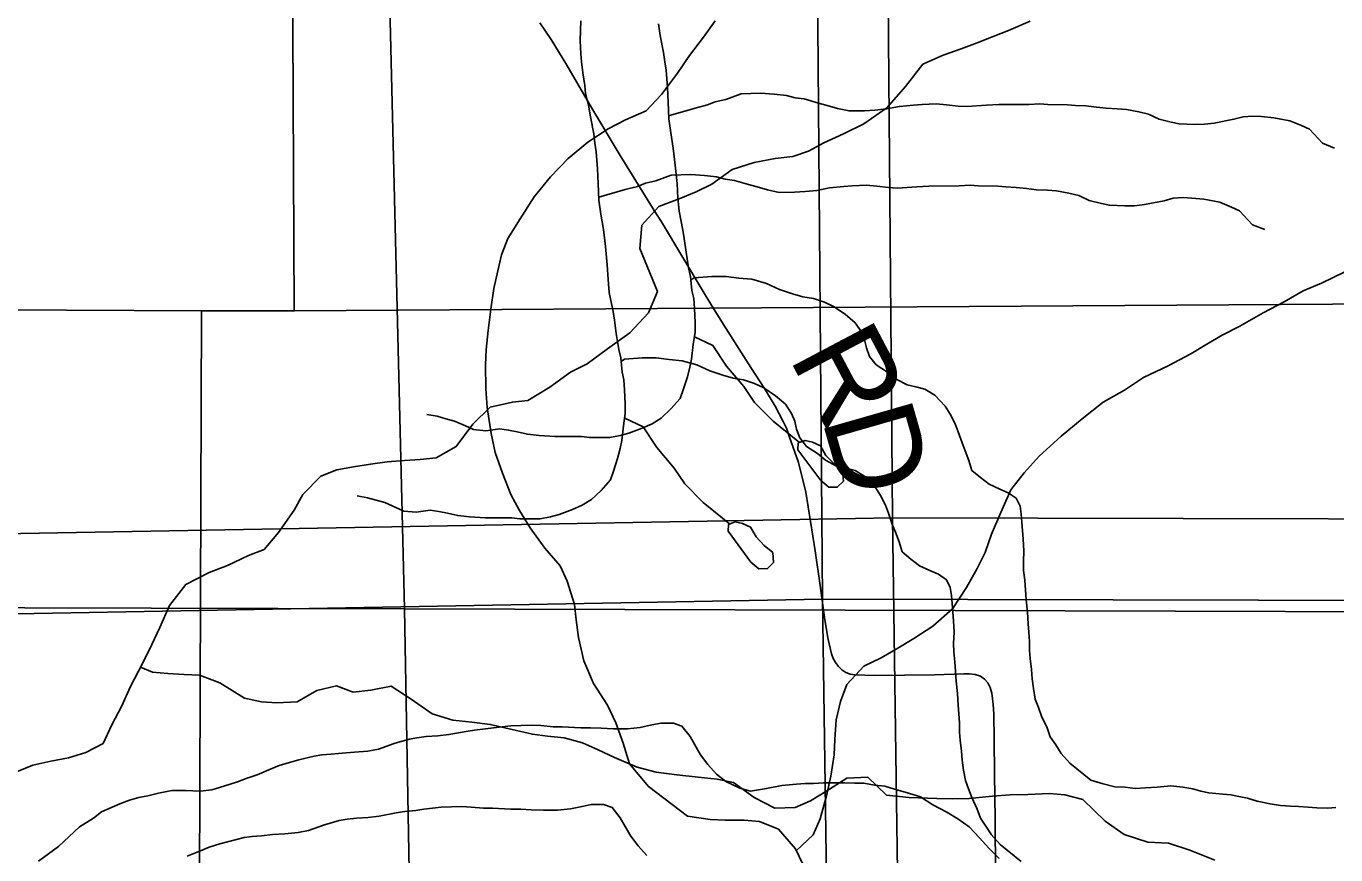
# Model space of a CAD drawing. Extents: x -21.1 to 50.3, y -4.9 to 22.1.
# Drawn here: x 6.307 to 7.119, y 16.789 to 17.303 of the extents above; entities that cross this region are included whole.
import ezdxf

# ---------------------------------------------------------------- set-up
doc = ezdxf.new("R2010")
doc.units = 0
for name, color, linetype in [('GM_X_Minor_Lake', 7, 'Continuous'), ('GM_X_Minor_River', 7, 'Continuous'), ('GM_X_Section', 7, 'Continuous'), ('GM_X_Township_Road', 7, 'Continuous'), ('GM_X_Township_Road_Text', 7, 'Continuous')]:
    doc.layers.add(name, color=color, linetype=linetype)

msp = doc.modelspace()

# ---------------------------------------------------------------- linework, layer by layer
at = {"layer": 'GM_X_Minor_Lake'}
for points in [[(6.79961, 17.0207), (6.80459, 17.01658), (6.8099, 17.01663), (6.81365, 17.02047), (6.8132, 17.02653), (6.80784, 17.03103), (6.80285, 17.03629), (6.79937, 17.04232), (6.79442, 17.04455), (6.78985, 17.04564), (6.7857, 17.04408), (6.78537, 17.0399)], [(6.78537, 17.0399), (6.79961, 17.0207)], [(6.75633, 16.97018), (6.7613, 16.96606), (6.76661, 16.96611), (6.77036, 16.96995), (6.76991, 16.97602), (6.76455, 16.98051), (6.75956, 16.98577), (6.75608, 16.99181), (6.75113, 16.99403), (6.74656, 16.99512), (6.74241, 16.99356), (6.74208, 16.98938)], [(6.74208, 16.98938), (6.75633, 16.97018)]]:
    msp.add_lwpolyline(points, dxfattribs=at)
at = {"layer": 'GM_X_Minor_River'}
for points in [[(6.29709, 16.83866), (6.31085, 16.84415), (6.32191, 16.84665), (6.33295, 16.84876), (6.34364, 16.85201), (6.35436, 16.85755), (6.35986, 16.86924), (6.36612, 16.88092), (6.37124, 16.89262), (6.37907, 16.9077), (6.38456, 16.91901), (6.38966, 16.92957), (6.39557, 16.94315), (6.40565, 16.9563), (6.4202, 16.96367), (6.43166, 16.96806), (6.44467, 16.97432), (6.45423, 16.97797), (6.46313, 16.98847), (6.47284, 17.00238), (6.47831, 17.01218), (6.48949, 17.0234), (6.49943, 17.02743), (6.50972, 17.02917), (6.52038, 17.03091), (6.53066, 17.03227), (6.54131, 17.03325), (6.55119, 17.03386), (6.56108, 17.03485), (6.57334, 17.04188), (6.58381, 17.05578), (6.59461, 17.06625), (6.60834, 17.06946), (6.61785, 17.07046), (6.63165, 17.0786), (6.64433, 17.08791), (6.65466, 17.09307), (6.66734, 17.10237), (6.68117, 17.11242), (6.69276, 17.12478), (6.69828, 17.13799), (6.6873, 17.16475), (6.68866, 17.17917), (6.6991, 17.19078), (6.71285, 17.19589), (6.72241, 17.19992), (6.73198, 17.20472), (6.74465, 17.21364), (6.75839, 17.21799), (6.77135, 17.22045), (6.78238, 17.22181), (6.79193, 17.22508), (6.8015, 17.23025), (6.81374, 17.23576), (6.82638, 17.24203), (6.84059, 17.25207), (6.85218, 17.26519), (6.86303, 17.27908), (6.87566, 17.28459), (6.88673, 17.2886), (6.89666, 17.29225), (6.9066, 17.29628), (6.91615, 17.29993), (6.92954, 17.3058)], [(6.65075, 17.30598), (6.65044, 17.29382), (6.65087, 17.28547), (6.65128, 17.28053), (6.65208, 17.2737), (6.65326, 17.26573), (6.65367, 17.26079), (6.65562, 17.25358), (6.6568, 17.24637), (6.65876, 17.23575), (6.65955, 17.23005), (6.66035, 17.22474), (6.66117, 17.21411), (6.6616, 17.20499), (6.66203, 17.19474), (6.66323, 17.18601), (6.6648, 17.17652), (6.666, 17.16589), (6.66721, 17.1545), (6.66764, 17.14539), (6.66845, 17.13741), (6.6708, 17.12565), (6.67159, 17.12033), (6.67277, 17.11198), (6.67435, 17.10211), (6.67552, 17.0968), (6.67634, 17.08807), (6.6775, 17.08314), (6.67792, 17.07706), (6.67835, 17.06833), (6.67838, 17.06225), (6.67728, 17.05465), (6.67619, 17.04552), (6.67508, 17.04058), (6.67359, 17.03449), (6.67097, 17.0265), (6.6691, 17.02117), (6.66342, 17.01468), (6.65737, 17.00895), (6.65168, 17.0055), (6.6456, 17.00281), (6.63724, 16.99972), (6.63192, 16.99818), (6.62546, 16.997), (6.6129, 16.99693), (6.60795, 16.99767), (6.59158, 16.99758), (6.58168, 16.99828), (6.57444, 16.999), (6.56796, 17.00049), (6.56263, 17.0016), (6.55729, 17.00233), (6.54855, 17.00114), (6.54093, 17.00186), (6.53597, 17.00411), (6.5291, 17.00711), (6.52376, 17.0086), (6.51843, 17.01009), (6.51195, 17.0112)], [(6.78843, 16.78286), (6.78393, 16.79238), (6.77339, 16.80458), (6.76166, 16.80921), (6.75218, 16.81002), (6.74041, 16.8101), (6.73093, 16.81053), (6.7169, 16.81252), (6.69274, 16.83088), (6.68107, 16.84499), (6.67698, 16.85791), (6.67251, 16.87046), (6.66727, 16.8815), (6.65863, 16.89483), (6.65265, 16.9089), (6.64933, 16.92334), (6.64788, 16.93435), (6.64681, 16.94384), (6.64235, 16.95829), (6.63786, 16.9678), (6.62844, 16.97886), (6.61942, 16.99144), (6.61266, 17.0021), (6.60741, 17.012), (6.60219, 17.02531), (6.59772, 17.03824), (6.59514, 17.05002), (6.59259, 17.06597), (6.5919, 17.07773), (6.59162, 17.09253), (6.59207, 17.10201), (6.59328, 17.11377), (6.59489, 17.12704), (6.59687, 17.13993), (6.59922, 17.15091), (6.60156, 17.16076), (6.60542, 17.17098), (6.61309, 17.18308), (6.62191, 17.19668), (6.63186, 17.20914), (6.64294, 17.22045), (6.65515, 17.23062), (6.66772, 17.23889), (6.67839, 17.24452), (6.69133, 17.25013), (6.70088, 17.26031), (6.71083, 17.27353), (6.71811, 17.28449), (6.72692, 17.29582), (6.73419, 17.30602)], [(6.6989, 17.3041), (6.70009, 17.29689), (6.70205, 17.28626), (6.70284, 17.28057), (6.70363, 17.27526), (6.70445, 17.26462), (6.70489, 17.25551), (6.70532, 17.24525), (6.70651, 17.23652), (6.70809, 17.22704), (6.70929, 17.21641), (6.7105, 17.20502), (6.71093, 17.1959), (6.71173, 17.18793), (6.71408, 17.17616), (6.71487, 17.17085), (6.71606, 17.1625), (6.71764, 17.15263), (6.71881, 17.14732), (6.71962, 17.13859), (6.72079, 17.13366), (6.72121, 17.12758), (6.72164, 17.11884), (6.72167, 17.11277), (6.72057, 17.10516), (6.71948, 17.09604), (6.71837, 17.09109), (6.71688, 17.08501), (6.71426, 17.07702), (6.71239, 17.07169), (6.70671, 17.0652), (6.70065, 17.05947), (6.69497, 17.05602), (6.68889, 17.05333), (6.68053, 17.05024), (6.67521, 17.04869), (6.66875, 17.04752), (6.65619, 17.04745), (6.65123, 17.04818), (6.63487, 17.04809), (6.62497, 17.0488), (6.61773, 17.04952), (6.61125, 17.051), (6.60592, 17.05211), (6.60058, 17.05284), (6.59184, 17.05166), (6.58422, 17.05238), (6.57926, 17.05463), (6.57239, 17.05763), (6.56705, 17.05912), (6.56172, 17.06061), (6.55524, 17.06171)], [(6.70525, 17.24708), (6.72165, 17.2518), (6.72926, 17.25374), (6.73419, 17.25567), (6.74065, 17.25722), (6.75015, 17.26069), (6.76233, 17.26114), (6.77071, 17.26043), (6.77833, 17.25971), (6.78366, 17.25822), (6.78938, 17.25749), (6.79815, 17.25488), (6.80501, 17.25302), (6.80996, 17.25152), (6.81721, 17.25004), (6.82672, 17.2501), (6.83319, 17.25051), (6.84042, 17.25131), (6.8484, 17.25287), (6.85715, 17.25368), (6.86248, 17.25409), (6.87123, 17.25452), (6.8777, 17.25379), (6.88494, 17.25307), (6.89027, 17.25272), (6.90245, 17.25355), (6.91006, 17.25397), (6.92871, 17.25407), (6.93556, 17.25449), (6.94051, 17.25414), (6.95269, 17.25382), (6.95764, 17.25347), (6.96411, 17.25312), (6.97059, 17.2524), (6.97668, 17.25167), (6.98354, 17.25133), (6.98925, 17.25098), (6.99687, 17.2495), (7.00297, 17.24802), (7.00946, 17.24502), (7.01708, 17.24316), (7.02203, 17.24205), (7.03155, 17.24172), (7.03764, 17.24175), (7.04373, 17.24254), (7.0559, 17.24489), (7.0616, 17.24644), (7.06768, 17.24685), (7.07301, 17.2465), (7.08063, 17.24578), (7.09054, 17.24394), (7.09779, 17.24094), (7.10275, 17.23869), (7.11079, 17.22999), (7.11842, 17.22699)], [(6.66196, 17.19656), (6.67837, 17.20129), (6.68597, 17.20323), (6.6909, 17.20515), (6.69737, 17.20671), (6.70686, 17.21018), (6.71904, 17.21062), (6.72742, 17.20991), (6.73504, 17.20919), (6.74037, 17.2077), (6.74609, 17.20697), (6.75486, 17.20436), (6.76172, 17.2025), (6.76667, 17.20101), (6.77392, 17.19953), (6.78343, 17.19958), (6.7899, 17.19999), (6.79713, 17.20079), (6.80511, 17.20236), (6.81386, 17.20316), (6.81919, 17.20357), (6.82794, 17.204), (6.83442, 17.20328), (6.84165, 17.20256), (6.84698, 17.20221), (6.85916, 17.20303), (6.86677, 17.20345), (6.88542, 17.20356), (6.89227, 17.20397), (6.89722, 17.20362), (6.9094, 17.20331), (6.91435, 17.20295), (6.92083, 17.20261), (6.9273, 17.20188), (6.93339, 17.20116), (6.94025, 17.20082), (6.94596, 17.20047), (6.95358, 17.19899), (6.95968, 17.1975), (6.96617, 17.1945), (6.97379, 17.19264), (6.97874, 17.19153), (6.98826, 17.1912), (6.99435, 17.19123), (7.00044, 17.19203), (7.01261, 17.19437), (7.01831, 17.19592), (7.02439, 17.19634), (7.02973, 17.19599), (7.03734, 17.19527), (7.04725, 17.19342), (7.0545, 17.19042), (7.05946, 17.18817), (7.0675, 17.17948), (7.07513, 17.17648)], [(6.71901, 17.14522), (6.7211, 17.14657), (6.73214, 17.14739), (6.74089, 17.14744), (6.74889, 17.14634), (6.75689, 17.14563), (6.76604, 17.14302), (6.77405, 17.13926), (6.78206, 17.13665), (6.78854, 17.13478), (6.79502, 17.13368), (6.80188, 17.13144), (6.80761, 17.12881), (6.81486, 17.12391), (6.82099, 17.11863), (6.82482, 17.11295), (6.82676, 17.10802), (6.82792, 17.10309), (6.82986, 17.09778), (6.83407, 17.09248), (6.84095, 17.08796), (6.84592, 17.08381), (6.85318, 17.08005), (6.85851, 17.07894), (6.86423, 17.07745), (6.87034, 17.07369), (6.87685, 17.06689), (6.87992, 17.06196), (6.883, 17.0559), (6.88493, 17.05098), (6.88725, 17.04415), (6.88918, 17.03922), (6.8915, 17.03316), (6.89344, 17.02709), (6.89879, 17.02256), (6.90415, 17.01841), (6.91063, 17.01541), (6.91597, 17.01316), (6.92094, 17.00977), (6.92325, 17.00484), (6.92404, 16.99991), (6.92445, 16.99497), (6.92527, 16.98434), (6.92569, 16.97712), (6.92535, 16.97028), (6.92538, 16.96496), (6.92617, 16.95889), (6.927, 16.94674), (6.92781, 16.93914), (6.92823, 16.93193), (6.92864, 16.92661), (6.92905, 16.92092), (6.92908, 16.91522), (6.92949, 16.91028), (6.93029, 16.90345), (6.9307, 16.89775), (6.9315, 16.89168), (6.93268, 16.88523), (6.93461, 16.87992), (6.93654, 16.87461), (6.94001, 16.86741), (6.94194, 16.86173), (6.9454, 16.8568), (6.94885, 16.85151), (6.95422, 16.84546), (6.96722, 16.83489), (6.97484, 16.83265), (6.98208, 16.83079), (6.98855, 16.83045), (6.99465, 16.82972), (7.00112, 16.83014), (7.00835, 16.83056), (7.01672, 16.83136), (7.02433, 16.83064), (7.03043, 16.82954), (7.03539, 16.82805), (7.04034, 16.82693), (7.0491, 16.82622), (7.05405, 16.82587), (7.05901, 16.82475), (7.06434, 16.82364), (7.07044, 16.82178), (7.07844, 16.8203), (7.08492, 16.8192), (7.09101, 16.81885), (7.09596, 16.8185), (7.10205, 16.81815), (7.10738, 16.8178), (7.11424, 16.81746), (7.11918, 16.81786)], [(6.78451, 16.79115), (6.795, 16.80103), (6.79924, 16.81087), (6.80313, 16.82526), (6.80586, 16.83739), (6.80785, 16.85066), (6.80829, 16.86014), (6.80913, 16.87228), (6.81186, 16.88364), (6.81572, 16.89424), (6.82642, 16.90556), (6.83708, 16.9108), (6.84737, 16.91681), (6.85727, 16.92282), (6.86909, 16.93033), (6.8813, 16.94126), (6.89012, 16.95449), (6.89665, 16.96621), (6.90164, 16.97604), (6.90551, 16.9874), (6.91129, 17.00102), (6.91746, 17.01502), (6.92588, 17.0256), (6.93505, 17.03578), (6.94879, 17.04822), (6.96177, 17.05914), (6.97474, 17.06931), (6.98807, 17.07681), (6.99988, 17.08471), (7.01511, 17.09182), (7.0292, 17.09932), (7.0391, 17.10533), (7.04863, 17.11097), (7.05967, 17.11659), (7.07414, 17.12485), (7.08709, 17.1316), (7.0989, 17.13835), (7.11031, 17.14322), (7.12478, 17.15033)], [(6.72127, 17.11001), (6.73269, 17.1046), (6.74118, 17.09179), (6.75194, 17.079), (6.75849, 17.06921), (6.77, 17.05757), (6.78635, 17.04432)], [(6.67572, 17.09471), (6.67781, 17.09606), (6.68885, 17.09687), (6.6976, 17.09693), (6.7056, 17.09583), (6.7136, 17.09511), (6.72275, 17.0925), (6.73076, 17.08875), (6.73877, 17.08613), (6.74525, 17.08427), (6.75173, 17.08316), (6.75859, 17.08092), (6.76432, 17.07829), (6.77158, 17.07339), (6.7777, 17.06811), (6.78153, 17.06243), (6.78347, 17.0575), (6.78463, 17.05257), (6.78657, 17.04726), (6.79078, 17.04197), (6.79766, 17.03745), (6.80263, 17.0333), (6.80989, 17.02954), (6.81522, 17.02843), (6.82094, 17.02694), (6.82705, 17.02317), (6.83356, 17.01637), (6.83663, 17.01145), (6.83971, 17.00539), (6.84164, 17.00046), (6.84396, 16.99363), (6.84589, 16.98871), (6.84821, 16.98264), (6.85015, 16.97657), (6.8555, 16.97204), (6.86086, 16.9679), (6.86734, 16.96489), (6.87268, 16.96264), (6.87765, 16.95925), (6.87996, 16.95432), (6.88075, 16.94939), (6.88116, 16.94445), (6.88198, 16.93382), (6.8824, 16.92661), (6.88206, 16.91976), (6.88209, 16.91445), (6.88288, 16.90837), (6.88371, 16.89622), (6.88452, 16.88863), (6.88494, 16.88141), (6.88535, 16.8761), (6.88576, 16.8704), (6.88579, 16.8647), (6.8862, 16.85977), (6.887, 16.85293), (6.88741, 16.84724), (6.88821, 16.84116), (6.88939, 16.83471), (6.89132, 16.8294), (6.89325, 16.8241), (6.89672, 16.8169), (6.89865, 16.81121), (6.90211, 16.80629), (6.90556, 16.80099), (6.91093, 16.79494), (6.92393, 16.78437)], [(6.67799, 17.05949), (6.6894, 17.05409), (6.69789, 17.04128), (6.70865, 17.02849), (6.7152, 17.01869), (6.72671, 17.00705), (6.74306, 16.9938)], [(6.37766, 16.90498), (6.38506, 16.90191), (6.39454, 16.90101), (6.40478, 16.90047), (6.41427, 16.89994), (6.42673, 16.8952), (6.44216, 16.88585), (6.45276, 16.88341), (6.46224, 16.88288), (6.47479, 16.88345), (6.48705, 16.89048), (6.49925, 16.89333), (6.50944, 16.88938), (6.52048, 16.89073), (6.53305, 16.8932), (6.54546, 16.88504), (6.55861, 16.8761), (6.57146, 16.87211), (6.58322, 16.87079), (6.59459, 16.86948), (6.60822, 16.86623), (6.62071, 16.86338), (6.63018, 16.8621), (6.64042, 16.86118), (6.65177, 16.85797), (6.66158, 16.85364), (6.67176, 16.84893), (6.68572, 16.84302), (6.69744, 16.8398), (6.71033, 16.83809), (6.72361, 16.83675), (6.73536, 16.83543), (6.74558, 16.83337), (6.75835, 16.82406), (6.77116, 16.81741), (6.7837, 16.81798), (6.79326, 16.82201), (6.80285, 16.82795), (6.81589, 16.8361), (6.82881, 16.83667), (6.84041, 16.82548), (6.85445, 16.82412), (6.87153, 16.82348), (6.8814, 16.82333), (6.89166, 16.82356), (6.90612, 16.82486), (6.91714, 16.82583), (6.92816, 16.82604), (6.94147, 16.8266), (6.95095, 16.8257), (6.9623, 16.82286), (6.97614, 16.80936), (6.98779, 16.80121), (7.00253, 16.79642), (7.01543, 16.79585), (7.02866, 16.79147), (7.04413, 16.78515)], [(6.91039, 16.78634), (6.90388, 16.79276), (6.89814, 16.79919), (6.89163, 16.80599), (6.88475, 16.81089), (6.87788, 16.81503), (6.8691, 16.81954), (6.86146, 16.82444), (6.85192, 16.82742), (6.84544, 16.82929), (6.83934, 16.83116), (6.83287, 16.83188), (6.82639, 16.83298), (6.82068, 16.83295), (6.81459, 16.8333), (6.80127, 16.83323), (6.79518, 16.83281), (6.78985, 16.83279), (6.78452, 16.83238), (6.77539, 16.83157), (6.76589, 16.82962), (6.76094, 16.82883), (6.756, 16.82804), (6.74952, 16.82991), (6.74074, 16.83404), (6.73501, 16.83856), (6.72964, 16.84461), (6.72504, 16.85067), (6.72158, 16.85673), (6.71851, 16.86203), (6.71352, 16.86846), (6.70818, 16.87033), (6.70057, 16.87029), (6.69487, 16.86912), (6.68765, 16.86756), (6.67966, 16.86675), (6.6709, 16.86671), (6.66329, 16.86705), (6.65681, 16.86739), (6.65072, 16.86736), (6.6393, 16.86805), (6.63359, 16.86802), (6.62598, 16.86874), (6.62026, 16.86909), (6.60733, 16.86864), (6.59667, 16.86744), (6.59173, 16.86666), (6.58488, 16.86586), (6.57956, 16.86507), (6.56891, 16.86311), (6.56206, 16.86232), (6.55483, 16.8619), (6.54913, 16.8611), (6.54419, 16.86032), (6.53507, 16.85761), (6.52519, 16.85414), (6.51872, 16.85296), (6.51036, 16.85216), (6.50275, 16.85173), (6.4959, 16.85094), (6.49019, 16.85053), (6.48525, 16.84974), (6.47574, 16.84741), (6.47004, 16.84586), (6.46358, 16.84392), (6.45713, 16.84123), (6.44991, 16.83815), (6.44307, 16.83584), (6.43776, 16.83391), (6.4294, 16.8312), (6.4218, 16.82888), (6.41457, 16.82808), (6.40543, 16.82841), (6.39706, 16.82837), (6.38869, 16.8268), (6.38223, 16.82525), (6.37653, 16.82407), (6.37083, 16.82252), (6.36475, 16.82021), (6.35336, 16.81521), (6.34843, 16.81139), (6.33971, 16.80602), (6.32683, 16.79379), (6.31433, 16.78461)], [(6.69172, 16.78805), (6.68635, 16.7941), (6.68175, 16.80015), (6.67829, 16.80621), (6.67522, 16.81151), (6.67024, 16.81794), (6.6649, 16.81981), (6.65728, 16.81977), (6.65158, 16.8186), (6.64436, 16.81704), (6.63637, 16.81624), (6.62761, 16.81619), (6.62, 16.81653), (6.61352, 16.81687), (6.60744, 16.81684), (6.59601, 16.81754), (6.5903, 16.81751), (6.58269, 16.81822), (6.57698, 16.81857), (6.56404, 16.81812), (6.55338, 16.81693), (6.54844, 16.81614), (6.5416, 16.81534), (6.53627, 16.81455), (6.52562, 16.8126), (6.51877, 16.8118), (6.51155, 16.81138), (6.50584, 16.81059), (6.5009, 16.8098), (6.49178, 16.80709), (6.4819, 16.80362), (6.47544, 16.80245), (6.46707, 16.80164), (6.45946, 16.80122), (6.45261, 16.80042), (6.4469, 16.80001), (6.44196, 16.79922), (6.43245, 16.79689), (6.42675, 16.79534), (6.42029, 16.79341), (6.41384, 16.79071), (6.40662, 16.78764)]]:
    msp.add_lwpolyline(points, dxfattribs=at)
at = {"layer": 'GM_X_Section'}
for points in [[(5.45742, 18.14589), (6.46827, 18.13471), (6.47301, 17.12604), (6.41542, 17.12601), (5.45266, 17.13084)], [(6.46827, 18.13471), (7.46215, 18.13462), (7.47526, 17.13233), (7.40705, 17.13199), (6.47301, 17.12604)], [(5.81893, 17.99203), (6.83569, 18.01448), (6.84408, 16.99761), (5.83147, 16.97938)], [(6.83569, 18.01448), (7.84977, 17.99671), (7.85852, 16.9825), (7.38497, 16.99642), (6.84408, 16.99761)], [(5.48815, 17.97251), (6.51666, 17.95921), (6.54146, 16.94121), (5.52017, 16.94387)], [(5.77564, 17.94152), (6.7924, 17.96396), (6.8008, 16.94709), (5.78818, 16.92886)], [(7.54061, 17.96333), (7.56617, 16.93816), (6.54146, 16.94121), (6.51666, 17.95921)], [(6.7924, 17.96396), (7.80649, 17.9462), (7.81523, 16.93198), (7.34169, 16.9459), (6.8008, 16.94709)], [(5.45266, 17.13084), (6.41542, 17.12601), (6.41187, 16.12459), (5.44952, 16.13321)], [(6.47301, 17.12604), (7.40705, 17.13199), (7.42125, 16.12212), (6.41187, 16.12459), (6.41542, 17.12601)], [(5.83147, 16.97938), (6.84408, 16.99761), (6.85861, 15.97246), (5.84702, 15.96751)], [(6.84408, 16.99761), (7.38497, 16.99642), (7.85852, 16.9825), (7.86729, 15.96487), (7.36725, 15.97553), (6.85861, 15.97246)], [(6.54146, 16.94121), (6.55964, 15.91994), (6.50469, 15.92066), (5.53343, 15.91957), (5.52017, 16.94387)], [(5.78818, 16.92886), (6.8008, 16.94709), (6.81532, 15.92194), (5.80373, 15.91699)], [(7.56617, 16.93816), (7.57297, 15.92106), (7.52522, 15.9214), (6.55964, 15.91994), (6.54146, 16.94121)], [(6.8008, 16.94709), (7.34169, 16.9459), (7.81523, 16.93198), (7.824, 15.91436), (7.32396, 15.92501), (6.81532, 15.92194)]]:
    msp.add_lwpolyline(points, close=True, dxfattribs=at)
at = {"layer": 'GM_X_Township_Road'}
msp.add_lwpolyline([(6.9081, 16.77653), (6.90777, 16.81068), (6.90748, 16.83859), (6.90713, 16.86031), (6.90691, 16.87583), (6.90662, 16.88212), (6.90621, 16.88527), (6.9057, 16.88876), (6.90478, 16.89233), (6.90322, 16.89518), (6.90125, 16.89746), (6.89873, 16.8993), (6.89548, 16.90039), (6.89188, 16.90079), (6.88831, 16.90083), (6.87019, 16.90018), (6.83302, 16.89971), (6.82071, 16.90015), (6.8178, 16.90068), (6.81511, 16.90172), (6.81272, 16.90334), (6.81063, 16.90542), (6.80885, 16.90782), (6.80742, 16.91041), (6.80638, 16.9132), (6.80428, 16.92218), (6.80212, 16.93435), (6.79927, 16.95557), (6.79624, 16.97723), (6.7903, 17.01357), (6.78582, 17.03193), (6.78027, 17.04765), (6.77829, 17.05333), (6.77632, 17.0573), (6.77143, 17.06694), (6.7647, 17.07778), (6.75625, 17.09086), (6.75044, 17.09997), (6.73921, 17.11755), (6.73136, 17.13013), (6.72662, 17.1381), (6.70076, 17.18117), (6.69623, 17.18823), (6.67513, 17.2224), (6.65764, 17.25171), (6.64201, 17.27851), (6.63232, 17.29444), (6.62543, 17.3048)], dxfattribs=at)

# ---------------------------------------------------------------- texts
at = {"layer": 'GM_X_Township_Road_Text'}
for s, rotation, p in [('R', 297.85944, (6.77938, 17.09742)), ('D', 286.02897, (6.80003, 17.05903))]:
    msp.add_text(s, height=0.05682, rotation=rotation, dxfattribs=at).set_placement(p)

doc.saveas('drawing.dxf')
